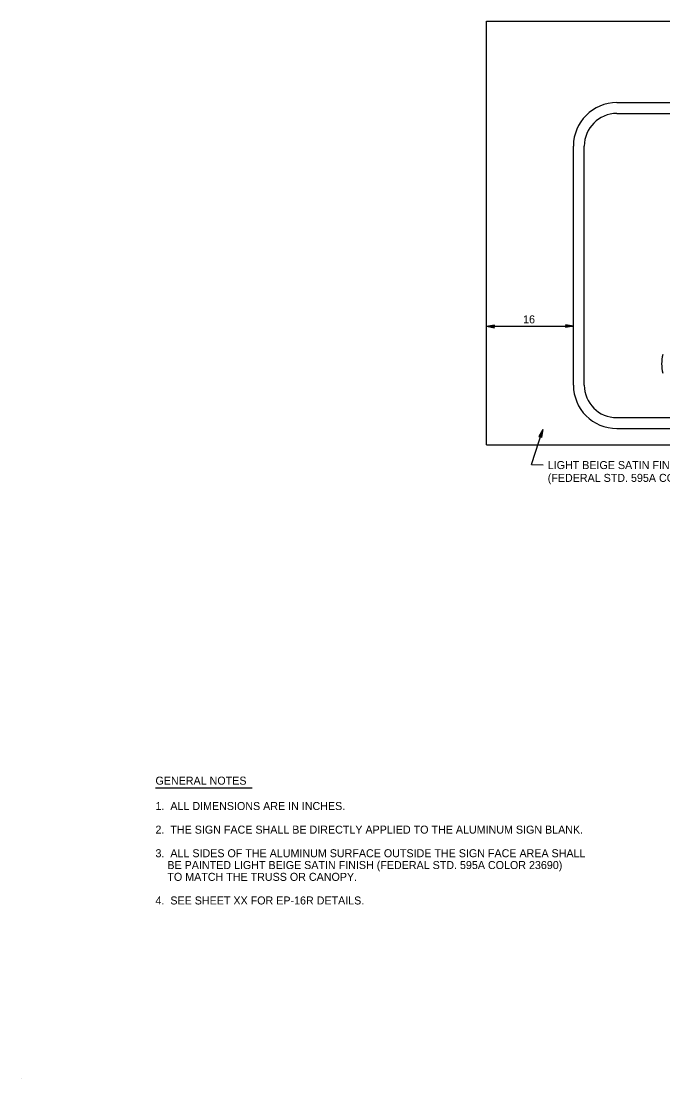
# Model space of a CAD drawing. Extents: x 60714 to 61340, y 9359 to 9729.
# Drawn here: x 60713.6 to 60938.1, y 9359 to 9729 of the extents above; entities that cross this region are included whole.
import ezdxf

# ---------------------------------------------------------------- set-up
doc = ezdxf.new("R2010")
doc.units = 0
for name, color, linetype in [('1', 7, 'Continuous'), ('2', 7, 'Continuous'), ('52', 7, 'Continuous'), ('AdhocPoint_dp', 7, 'Continuous'), ('GSBWFill', 7, 'Continuous'), ('SignPanel', 7, 'Continuous'), ('TextNotes', 7, 'Continuous')]:
    doc.layers.add(name, color=color, linetype=linetype)

msp = doc.modelspace()

# ---------------------------------------------------------------- linework, layer by layer
at = {"layer": '1'}
for p, q in [((60876.38, 9622.25), (60906.78, 9622.25)), ((60892.13, 9573.84), (60896.04, 9586.08)), ((60892.13, 9573.84), (60896.24, 9573.81))]:
    msp.add_line(p, q, dxfattribs=at)
at = {"layer": '2'}
for p, q in [((60876.38, 9580.77), (60876.38, 9728.97)), ((60876.38, 9728.97), (61210.79, 9728.97)), ((60876.38, 9580.77), (61210.79, 9580.77))]:
    msp.add_line(p, q, dxfattribs=at)
at = {"layer": '52'}
for p, q in [((60876.38, 9622.25), (60879.16, 9622.69)), ((60876.38, 9622.25), (60879.04, 9622.44)), ((60876.38, 9622.25), (60879.14, 9621.71)), ((60876.38, 9622.25), (60879.04, 9621.97)), ((60878.94, 9622.21), (60879.16, 9622.69)), ((60879.14, 9621.71), (60878.94, 9622.21)), ((60904.23, 9622.29), (60904.01, 9621.81)), ((60906.78, 9622.25), (60904.01, 9621.81)), ((60906.78, 9622.25), (60904.02, 9622.79)), ((60904.02, 9622.79), (60904.23, 9622.29)), ((60906.78, 9622.25), (60904.12, 9622.06)), ((60906.78, 9622.25), (60904.13, 9622.53)), ((60896.04, 9586.08), (60894.69, 9583.62)), ((60894.69, 9583.62), (60895.22, 9583.66)), ((60896.04, 9586.08), (60894.97, 9583.64)), ((60895.22, 9583.66), (60895.62, 9583.3)), ((60896.04, 9586.08), (60895.41, 9583.49)), ((60896.04, 9586.08), (60895.62, 9583.3))]:
    msp.add_line(p, q, dxfattribs=at)
at = {"layer": 'AdhocPoint_dp'}
msp.add_line((60713.58, 9358.97), (60713.58, 9358.97), dxfattribs=at)
at = {"layer": 'GSBWFill'}
msp.add_arc((60950.41, 9609.07), 12.77, 165.0382, 194.9618, dxfattribs=at)
msp.add_arc((60950.41, 9609.07), 12.77, 165.0382, 194.9618, dxfattribs=at)
msp.add_arc((60950.41, 9609.07), 12.77, 165.0382, 194.9618, dxfattribs=at)
at = {"layer": 'SignPanel'}
for p, q in [((60921.98, 9700.47), (61165.18, 9700.47)), ((60921.98, 9696.67), (61165.18, 9696.67)), ((60906.78, 9601.67), (60906.78, 9685.27)), ((60910.58, 9601.67), (60910.58, 9685.27)), ((60921.98, 9590.27), (61165.18, 9590.27)), ((60921.98, 9586.47), (61165.18, 9586.47))]:
    msp.add_line(p, q, dxfattribs=at)
for centre, radius, start, end in [((60921.98, 9685.27), 15.2, 90, 180), ((60921.98, 9685.27), 11.4, 90, 180), ((60921.98, 9601.67), 15.2, 180, 270), ((60921.98, 9601.67), 11.4, 180, 270)]:
    msp.add_arc(centre, radius, start, end, dxfattribs=at)
at = {"layer": 'TextNotes'}
msp.add_line((60760.58, 9460.81), (60794.45, 9460.81), dxfattribs=at)

# ---------------------------------------------------------------- texts
at = {"layer": '1'}
for s, p in [('16', (60889.18, 9623.25)), ('LIGHT BEIGE SATIN FINISH', (60897.8, 9572.28)), ('(FEDERAL STD. 595A COLOR 23690)', (60897.8, 9567.8))]:
    msp.add_text(s, height=2.8, dxfattribs=at).set_placement(p)
at = {"layer": 'TextNotes'}
for s, p in [('GENERAL NOTES', (60760.58, 9461.88)), ('1.  ALL DIMENSIONS ARE IN INCHES.', (60760.58, 9453.01)), ('2.  THE SIGN FACE SHALL BE DIRECTLY APPLIED TO THE ALUMINUM SIGN BLANK.', (60760.58, 9444.75)), ('3.  ALL SIDES OF THE ALUMINUM SURFACE OUTSIDE THE SIGN FACE AREA SHALL', (60760.58, 9436.49)), ('    BE PAINTED LIGHT BEIGE SATIN FINISH (FEDERAL STD. 595A COLOR 23690)', (60760.58, 9432.36)), ('    TO MATCH THE TRUSS OR CANOPY.', (60760.58, 9428.23)), ('4.  SEE SHEET XX FOR EP-16R DETAILS.', (60760.58, 9419.97))]:
    msp.add_text(s, height=2.8, dxfattribs=at).set_placement(p)

doc.saveas('drawing.dxf')
